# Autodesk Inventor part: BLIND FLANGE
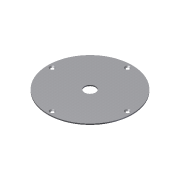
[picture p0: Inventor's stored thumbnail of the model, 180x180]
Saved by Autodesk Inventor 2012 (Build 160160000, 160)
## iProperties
Created: 2011-06
Part Number: BLIND FLANGE
Material: Stainless Steel, 440C
Document SubType Name: Modeling
Designer: Dimitris
Mass: 2099.89 g
Surface Area: 1237.43 cm^2
Volume: 270.953 cm^3
Density: 7.75 g/cm^3
Author: Dimitris
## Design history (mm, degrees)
sketch "Sketch1"
  geometry: C1 r 25 at (0, 0); C2 r 240 at (0, 0); 1 further point
  constraints: 2 centre point, 1 coincident
  dimensions: "d0" = 50 diameter of C1; "OD" = 480 diameter of C2
extrude "Extrusion1" new body sketch "Sketch1" distance "d2" = 5; taper "d3" = 0 deg
sketch "Sketch2"
  geometry: C1 r 240 at (0, 0) reference; 3 further points
  constraints: 2 vertical alignment, 1 coincident, 2 other
  dimensions: "d15" = 20 dimension on C1
hole "Hole1" sketch "Sketch2" at (0, 220) diameter "d5" = 11; stored, may be unused: countersink angle "d9" = 90 deg, drill point angle "d11" = 118 deg; dims "d6" = 6, "d7" = 23.5, "d8" = 2, "d10" = 8
pattern_circular "Circular Pattern1" dims angle "d13" = 360 deg
body "Solid1"
